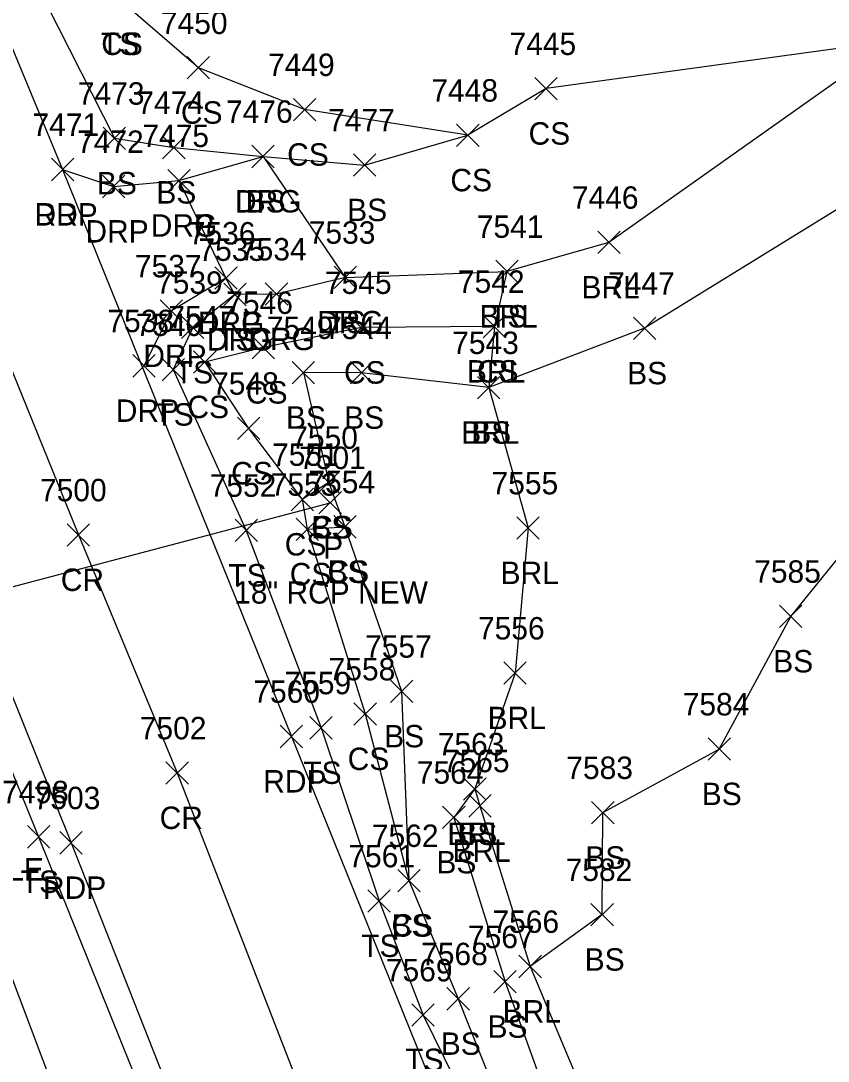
# Model space of a CAD drawing. Extents: x 1472233 to 1475777, y 540726 to 543442.
# Drawn here: x 1472800.2 to 1472872.2, y 540921.2 to 541014 of the extents above; entities that cross this region are included whole.
import ezdxf

# ---------------------------------------------------------------- set-up
doc = ezdxf.new("R2010")
doc.units = 0
for name, color, linetype in [('D_A', 7, 'Continuous'), ('D_C', 7, 'Continuous'), ('D_I', 7, 'Continuous'), ('D_TIC', 7, 'Continuous'), ('DCP', 7, 'Continuous'), ('L_A', 7, 'Continuous'), ('L_C', 7, 'Continuous'), ('L_I', 7, 'Continuous'), ('L_TIC', 7, 'Continuous'), ('LABL', 7, 'Continuous'), ('LELB', 7, 'Continuous'), ('LFNC', 7, 'Continuous'), ('P_A', 7, 'Continuous'), ('P_I', 7, 'Continuous'), ('P_TIC', 7, 'Continuous'), ('PET', 7, 'Continuous'), ('PRC', 7, 'Continuous'), ('R_A', 7, 'Continuous'), ('R_I', 7, 'Continuous'), ('R_TIC', 7, 'Continuous'), ('RDG', 7, 'Continuous'), ('RDP', 7, 'Continuous')]:
    doc.layers.add(name, color=color, linetype=linetype)

msp = doc.modelspace()

# ---------------------------------------------------------------- linework, layer by layer
at = {"layer": 'D_TIC'}
for points in [[(1472826.799, 540969.989), (1472828.799, 540971.989)], [(1472828.799, 540969.989), (1472826.799, 540971.989)]]:
    msp.add_lwpolyline(points, dxfattribs=at)
at = {"layer": 'DCP'}
msp.add_lwpolyline([(1472784.082, 540959.45), (1472827.799, 540970.989)], dxfattribs=at)
at = {"layer": 'L_TIC'}
for points in [[(1472815.038, 541008.798), (1472817.038, 541010.798)], [(1472817.038, 541008.798), (1472815.038, 541010.798)], [(1472846.067, 541006.931), (1472848.067, 541008.931)], [(1472848.067, 541006.931), (1472846.067, 541008.931)], [(1472824.52, 541005.054), (1472826.52, 541007.054)], [(1472826.52, 541005.054), (1472824.52, 541007.054)], [(1472807.54, 541002.497), (1472809.54, 541004.497)], [(1472809.54, 541002.497), (1472807.54, 541004.497)], [(1472839.089, 541002.772), (1472841.089, 541004.772)], [(1472841.089, 541002.772), (1472839.089, 541004.772)], [(1472812.847, 541001.676), (1472814.847, 541003.676)], [(1472814.847, 541001.676), (1472812.847, 541003.676)], [(1472820.816, 541000.878), (1472822.816, 541002.878)], [(1472822.816, 541000.878), (1472820.816, 541002.878)], [(1472829.877, 541000.108), (1472831.877, 541002.108)], [(1472831.877, 541000.108), (1472829.877, 541002.108)], [(1472851.685, 540993.214), (1472853.685, 540995.214)], [(1472853.685, 540993.214), (1472851.685, 540995.214)], [(1472842.58, 540990.617), (1472844.58, 540992.617)], [(1472844.58, 540990.617), (1472842.58, 540992.617)], [(1472842.58, 540990.617), (1472844.58, 540992.617)], [(1472844.58, 540990.617), (1472842.58, 540992.617)], [(1472828.148, 540990.092), (1472830.148, 540992.092)], [(1472830.148, 540990.092), (1472828.148, 540992.092)], [(1472818.305, 540988.563), (1472820.305, 540990.563)], [(1472820.305, 540988.563), (1472818.305, 540990.563)], [(1472814.529, 540985.625), (1472816.529, 540987.625)], [(1472816.529, 540985.625), (1472814.529, 540987.625)], [(1472829.592, 540985.615), (1472831.592, 540987.615)], [(1472831.592, 540985.615), (1472829.592, 540987.615)], [(1472841.46, 540985.708), (1472843.46, 540987.708)], [(1472843.46, 540985.708), (1472841.46, 540987.708)], [(1472841.46, 540985.708), (1472843.46, 540987.708)], [(1472843.46, 540985.708), (1472841.46, 540987.708)], [(1472854.863, 540985.554), (1472856.863, 540987.554)], [(1472856.863, 540985.554), (1472854.863, 540987.554)], [(1472820.841, 540983.832), (1472822.841, 540985.832)], [(1472822.841, 540983.832), (1472820.841, 540985.832)], [(1472812.792, 540981.863), (1472814.792, 540983.863)], [(1472814.792, 540981.863), (1472812.792, 540983.863)], [(1472815.615, 540982.535), (1472817.615, 540984.535)], [(1472817.615, 540982.535), (1472815.615, 540984.535)], [(1472824.415, 540981.599), (1472826.415, 540983.599)], [(1472826.415, 540981.599), (1472824.415, 540983.599)], [(1472829.611, 540981.581), (1472831.611, 540983.581)], [(1472831.611, 540981.581), (1472829.611, 540983.581)], [(1472840.948, 540980.253), (1472842.948, 540982.253)], [(1472842.948, 540980.253), (1472840.948, 540982.253)], [(1472840.948, 540980.253), (1472842.948, 540982.253)], [(1472842.948, 540980.253), (1472840.948, 540982.253)], [(1472819.523, 540976.623), (1472821.523, 540978.623)], [(1472821.523, 540976.623), (1472819.523, 540978.623)], [(1472826.673, 540971.801), (1472828.673, 540973.801)], [(1472828.673, 540971.801), (1472826.673, 540973.801)], [(1472826.673, 540971.801), (1472828.673, 540973.801)], [(1472828.673, 540971.801), (1472826.673, 540973.801)], [(1472824.306, 540970.277), (1472826.306, 540972.277)], [(1472826.306, 540970.277), (1472824.306, 540972.277)], [(1472824.306, 540970.277), (1472826.306, 540972.277)], [(1472826.306, 540970.277), (1472824.306, 540972.277)], [(1472819.307, 540967.515), (1472821.307, 540969.515)], [(1472821.307, 540967.515), (1472819.307, 540969.515)], [(1472824.754, 540967.615), (1472826.754, 540969.615)], [(1472826.754, 540967.615), (1472824.754, 540969.615)], [(1472824.754, 540967.615), (1472826.754, 540969.615)], [(1472826.754, 540967.615), (1472824.754, 540969.615)], [(1472828.118, 540967.833), (1472830.118, 540969.833)], [(1472830.118, 540967.833), (1472828.118, 540969.833)], [(1472828.118, 540967.833), (1472830.118, 540969.833)], [(1472830.118, 540967.833), (1472828.118, 540969.833)], [(1472844.463, 540967.733), (1472846.463, 540969.733)], [(1472846.463, 540967.733), (1472844.463, 540969.733)], [(1472867.901, 540959.845), (1472869.901, 540961.845)], [(1472869.901, 540959.845), (1472867.901, 540961.845)], [(1472843.306, 540954.787), (1472845.306, 540956.787)], [(1472845.306, 540954.787), (1472843.306, 540956.787)], [(1472833.179, 540953.162), (1472835.179, 540955.162)], [(1472835.179, 540953.162), (1472833.179, 540955.162)], [(1472829.923, 540951.139), (1472831.923, 540953.139)], [(1472831.923, 540951.139), (1472829.923, 540953.139)], [(1472825.991, 540949.901), (1472827.991, 540951.901)], [(1472827.991, 540949.901), (1472825.991, 540951.901)], [(1472861.521, 540948.011), (1472863.521, 540950.011)], [(1472863.521, 540948.011), (1472861.521, 540950.011)], [(1472839.708, 540944.454), (1472841.708, 540946.454)], [(1472841.708, 540944.454), (1472839.708, 540946.454)], [(1472839.708, 540944.454), (1472841.708, 540946.454)], [(1472841.708, 540944.454), (1472839.708, 540946.454)], [(1472840.169, 540942.944), (1472842.169, 540944.944)], [(1472842.169, 540942.944), (1472840.169, 540944.944)], [(1472851.133, 540942.341), (1472853.133, 540944.341)], [(1472853.133, 540942.341), (1472851.133, 540944.341)], [(1472837.84, 540941.92), (1472839.84, 540943.92)], [(1472839.84, 540941.92), (1472837.84, 540943.92)], [(1472800.778, 540940.178), (1472802.778, 540942.178)], [(1472802.778, 540940.178), (1472800.778, 540942.178)], [(1472833.83, 540936.279), (1472835.83, 540938.279)], [(1472835.83, 540936.279), (1472833.83, 540938.279)], [(1472833.83, 540936.279), (1472835.83, 540938.279)], [(1472835.83, 540936.279), (1472833.83, 540938.279)], [(1472833.83, 540936.279), (1472835.83, 540938.279)], [(1472835.83, 540936.279), (1472833.83, 540938.279)], [(1472831.161, 540934.463), (1472833.161, 540936.463)], [(1472833.161, 540934.463), (1472831.161, 540936.463)], [(1472851.076, 540933.241), (1472853.076, 540935.241)], [(1472853.076, 540933.241), (1472851.076, 540935.241)], [(1472851.076, 540933.241), (1472853.076, 540935.241)], [(1472853.076, 540933.241), (1472851.076, 540935.241)], [(1472844.647, 540928.613), (1472846.647, 540930.613)], [(1472846.647, 540928.613), (1472844.647, 540930.613)], [(1472842.404, 540927.253), (1472844.404, 540929.253)], [(1472844.404, 540927.253), (1472842.404, 540929.253)], [(1472838.227, 540925.731), (1472840.227, 540927.731)], [(1472840.227, 540925.731), (1472838.227, 540927.731)], [(1472835.088, 540924.284), (1472837.088, 540926.284)], [(1472837.088, 540924.284), (1472835.088, 540926.284)]]:
    msp.add_lwpolyline(points, dxfattribs=at)
at = {"layer": 'LABL'}
msp.add_lwpolyline([(1472934.655, 541070.893), (1472902.081, 541045.593), (1472878.098, 541012.185), (1472852.685, 540994.214), (1472843.58, 540991.617), (1472842.46, 540986.708), (1472841.948, 540981.253), (1472845.463, 540968.733), (1472844.306, 540955.787), (1472840.708, 540945.454), (1472841.169, 540943.944), (1472845.647, 540929.613), (1472856.732, 540903.157), (1472864.122, 540875.89)], dxfattribs=at)
at = {"layer": 'LELB'}
for points in [[(1472694.167, 541336.696), (1472710.287, 541363.82), (1472724.01, 541367.466), (1472732.84, 541358.022), (1472735.8, 541341.686), (1472737.449, 541336.783), (1472738.598, 541320.922), (1472714.319, 541313.691), (1472692.632, 541308.438), (1472692.612, 541304.716), (1472694.988, 541295.507), (1472702.177, 541269.109), (1472714.985, 541232.255), (1472725.569, 541201.652), (1472739.903, 541163.717), (1472759.74, 541112.631), (1472772.204, 541081.833), (1472792.335, 541035.431), (1472808.54, 541003.497), (1472813.847, 541002.676), (1472821.816, 541001.878), (1472830.877, 541001.108)], [(1472670.29, 541260.535), (1472686.415, 541223.334), (1472701.444, 541180.389), (1472718.784, 541138.611), (1472733.582, 541098.786), (1472746.912, 541068.409), (1472763.757, 541024.882), (1472785.71, 540979.265), (1472793.399, 540961.673), (1472801.778, 540941.178), (1472816.419, 540904.832), (1472818.512, 540895.298), (1472814.198, 540883.956), (1472809.696, 540876.261)], [(1473012.541, 541139.744), (1472973.929, 541106.163), (1472947.713, 541083.914), (1472934.655, 541070.893), (1472913.615, 541035.573), (1472885.771, 541005.004), (1472855.863, 540986.554), (1472841.948, 540981.253), (1472830.611, 540982.581), (1472825.415, 540982.599), (1472827.673, 540972.801), (1472829.118, 540968.833), (1472834.179, 540954.162), (1472834.83, 540937.279)], [(1472878.098, 541012.185), (1472847.067, 541007.931), (1472840.089, 541003.772), (1472825.52, 541006.054), (1472816.038, 541009.798), (1472808.929, 541015.933)], [(1472830.877, 541001.108), (1472840.089, 541003.772)], [(1472829.148, 540991.092), (1472843.58, 540991.617)], [(1472819.305, 540989.563), (1472815.529, 540986.625), (1472813.792, 540982.863), (1472820.307, 540968.515), (1472826.991, 540950.901), (1472832.161, 540935.463), (1472836.088, 540925.284), (1472847.393, 540902.304), (1472856.125, 540872.911)], [(1472852.076, 540934.241), (1472852.133, 540943.341), (1472862.521, 540949.011), (1472868.901, 540960.845), (1472886.466, 540982.48), (1472900.227, 540986.595), (1472924.188, 540989.652), (1472936.306, 540957.429)], [(1472842.46, 540986.708), (1472830.592, 540986.615), (1472821.841, 540984.832), (1472816.615, 540983.535), (1472820.523, 540977.623), (1472825.306, 540971.277), (1472825.754, 540968.615), (1472830.923, 540952.139), (1472834.83, 540937.279)], [(1472827.673, 540972.801), (1472825.306, 540971.277)], [(1472825.754, 540968.615), (1472829.118, 540968.833)], [(1472840.708, 540945.454), (1472838.84, 540942.92), (1472843.404, 540928.253), (1472852.876, 540902.047), (1472859.438, 540874.022)], [(1472834.83, 540937.279), (1472839.227, 540926.731), (1472849.327, 540901.317), (1472857.11, 540873.311)], [(1472852.076, 540934.241), (1472845.647, 540929.613)]]:
    msp.add_lwpolyline(points, dxfattribs=at)
at = {"layer": 'LFNC'}
msp.add_lwpolyline([(1472795.796, 540938.094), (1472806.397, 540909.942), (1472809.332, 540901.951)], dxfattribs=at)
at = {"layer": 'P_TIC'}
for points in [[(1472802.92, 540999.712), (1472804.92, 541001.712)], [(1472804.92, 540999.712), (1472802.92, 541001.712)], [(1472804.328, 540967.116), (1472806.328, 540969.116)], [(1472806.328, 540967.116), (1472804.328, 540969.116)], [(1472823.335, 540949.135), (1472825.335, 540951.135)], [(1472825.335, 540949.135), (1472823.335, 540951.135)], [(1472813.147, 540945.879), (1472815.147, 540947.879)], [(1472815.147, 540945.879), (1472813.147, 540947.879)], [(1472803.68, 540939.646), (1472805.68, 540941.646)], [(1472805.68, 540939.646), (1472803.68, 540941.646)]]:
    msp.add_lwpolyline(points, dxfattribs=at)
at = {"layer": 'PET'}
for points in [[(1472697.311, 541267.538), (1472711.092, 541230.886), (1472722.856, 541201.141), (1472737.776, 541162.897), (1472758.044, 541112.1), (1472770.407, 541081.49), (1472789.888, 541034.489), (1472803.92, 541000.712), (1472824.335, 540950.135), (1472844.219, 540900.954), (1472854.974, 540872.188)], [(1472676.203, 541262.983), (1472690.882, 541224.88), (1472707.576, 541182.941), (1472724.138, 541140.869), (1472739.403, 541101.901), (1472752.537, 541070.172), (1472769.423, 541027.837), (1472788.076, 540983.085), (1472796.043, 540962.122), (1472804.68, 540940.646), (1472818.489, 540905.674), (1472822.827, 540894.44), (1472834.107, 540865.53)]]:
    msp.add_lwpolyline(points, dxfattribs=at)
at = {"layer": 'PRC'}
msp.add_lwpolyline([(1472686.993, 541264.398), (1472700.968, 541228.154), (1472717.266, 541187.04), (1472733.85, 541145.792), (1472749.416, 541105.972), (1472761.217, 541076.788), (1472779.652, 541031.291), (1472797.555, 540987.284), (1472805.328, 540968.116), (1472814.147, 540946.879), (1472828.528, 540909.935), (1472844.389, 540869.839)], dxfattribs=at)
at = {"layer": 'R_TIC'}
for points in [[(1472820.816, 541000.878), (1472822.816, 541002.878)], [(1472822.816, 541000.878), (1472820.816, 541002.878)], [(1472802.92, 540999.712), (1472804.92, 541001.712)], [(1472804.92, 540999.712), (1472802.92, 541001.712)], [(1472813.299, 540998.722), (1472815.299, 541000.722)], [(1472815.299, 540998.722), (1472813.299, 541000.722)], [(1472813.299, 540998.722), (1472815.299, 541000.722)], [(1472815.299, 540998.722), (1472813.299, 541000.722)], [(1472807.467, 540998.198), (1472809.467, 541000.198)], [(1472809.467, 540998.198), (1472807.467, 541000.198)], [(1472817.498, 540990.025), (1472819.498, 540992.025)], [(1472819.498, 540990.025), (1472817.498, 540992.025)], [(1472817.498, 540990.025), (1472819.498, 540992.025)], [(1472819.498, 540990.025), (1472817.498, 540992.025)], [(1472828.148, 540990.092), (1472830.148, 540992.092)], [(1472830.148, 540990.092), (1472828.148, 540992.092)], [(1472818.305, 540988.563), (1472820.305, 540990.563)], [(1472820.305, 540988.563), (1472818.305, 540990.563)], [(1472822.009, 540988.598), (1472824.009, 540990.598)], [(1472824.009, 540988.598), (1472822.009, 540990.598)], [(1472812.633, 540987.095), (1472814.633, 540989.095)], [(1472814.633, 540987.095), (1472812.633, 540989.095)], [(1472810.178, 540982.202), (1472812.178, 540984.202)], [(1472812.178, 540982.202), (1472810.178, 540984.202)]]:
    msp.add_lwpolyline(points, dxfattribs=at)
at = {"layer": 'RDG'}
msp.add_lwpolyline([(1472814.299, 540999.722), (1472821.816, 541001.878), (1472829.148, 540991.092), (1472823.009, 540989.598), (1472819.305, 540989.563), (1472818.498, 540991.025)], dxfattribs=at)
at = {"layer": 'RDP'}
msp.add_lwpolyline([(1472803.92, 541000.712), (1472808.467, 540999.198), (1472814.299, 540999.722), (1472818.498, 540991.025), (1472813.633, 540988.095), (1472811.178, 540983.202)], dxfattribs=at)

# ---------------------------------------------------------------- texts
at = {"layer": 'D_A'}
msp.add_text('P', height=2, dxfattribs=at).set_placement((1472827.177, 540965.989))
at = {"layer": 'D_C'}
msp.add_text('18" RCP NEW', height=2, dxfattribs=at).set_placement((1472819.232, 540961.989))
at = {"layer": 'D_I'}
msp.add_text('7501', height=2, dxfattribs=at).set_placement((1472825.028, 540973.989))
at = {"layer": 'L_A'}
for s, p in [('TS', (1472807.338, 541010.933)), ('CS', (1472807.37, 541010.933)), ('CS', (1472814.479, 541004.798)), ('CS', (1472845.508, 541002.931)), ('CS', (1472823.961, 541001.054)), ('CS', (1472838.53, 540998.772)), ('BS', (1472806.981, 540998.497)), ('BS', (1472812.288, 540997.676)), ('BS', (1472820.257, 540996.878)), ('BS', (1472829.318, 540996.108)), ('BRL', (1472850.229, 540989.214)), ('BRL', (1472841.123, 540986.617)), ('TS', (1472841.99, 540986.617)), ('TS', (1472827.558, 540986.092)), ('TS', (1472817.714, 540984.563)), ('TS', (1472813.938, 540981.625)), ('CS', (1472829.033, 540981.615)), ('BRL', (1472840.004, 540981.708)), ('CS', (1472840.901, 540981.708)), ('BS', (1472854.304, 540981.554)), ('CS', (1472820.282, 540979.832)), ('CS', (1472815.056, 540978.535)), ('TS', (1472812.201, 540977.863)), ('BS', (1472823.856, 540977.599)), ('BS', (1472829.052, 540977.581)), ('BS', (1472840.389, 540976.253)), ('BRL', (1472839.492, 540976.253)), ('CS', (1472818.964, 540972.623)), ('CS', (1472826.114, 540967.801)), ('BS', (1472826.114, 540967.801)), ('CS', (1472823.747, 540966.277)), ('CS', (1472823.747, 540966.277)), ('TS', (1472818.717, 540963.515)), ('CS', (1472824.195, 540963.615)), ('CS', (1472824.195, 540963.615)), ('CS', (1472827.559, 540963.833)), ('BS', (1472827.559, 540963.833)), ('BRL', (1472843.007, 540963.733)), ('BS', (1472867.341, 540955.845)), ('BRL', (1472841.849, 540950.787)), ('BS', (1472832.62, 540949.162)), ('CS', (1472829.364, 540947.139)), ('TS', (1472825.4, 540945.901)), ('BS', (1472860.962, 540944.011)), ('BRL', (1472838.251, 540940.454)), ('BS', (1472839.149, 540940.454)), ('BRL', (1472838.712, 540938.944)), ('BS', (1472850.574, 540938.341)), ('BS', (1472837.281, 540937.92)), ('TS', (1472800.188, 540936.178)), ('CS', (1472833.271, 540932.279)), ('BS', (1472833.271, 540932.279)), ('BS', (1472833.271, 540932.279)), ('TS', (1472830.57, 540930.463)), ('BS', (1472850.517, 540929.241)), ('BS', (1472850.517, 540929.241)), ('BRL', (1472843.19, 540924.613)), ('BS', (1472841.845, 540923.253)), ('BS', (1472837.668, 540921.731)), ('TS', (1472834.498, 540920.284))]:
    msp.add_text(s, height=2, dxfattribs=at).set_placement(p)
at = {"layer": 'L_C'}
msp.add_text('S.APPLE', height=2, dxfattribs=at).set_placement((1472791.095, 540937.279))
at = {"layer": 'L_I'}
for s, p in [('7450', (1472812.692, 541012.798)), ('7445', (1472843.807, 541010.931)), ('7449', (1472822.253, 541009.054)), ('7473', (1472805.281, 541006.497)), ('7448', (1472836.83, 541006.772)), ('7474', (1472810.588, 541005.676)), ('7476', (1472818.501, 541004.878)), ('7477', (1472827.617, 541004.108)), ('7446', (1472849.37, 540997.214)), ('7533', (1472825.888, 540994.092)), ('7541', (1472840.887, 540994.617)), ('7541', (1472840.887, 540994.617)), ('7535', (1472816.045, 540992.563)), ('7539', (1472812.261, 540989.625)), ('7545', (1472827.333, 540989.615)), ('7542', (1472839.201, 540989.708)), ('7542', (1472839.201, 540989.708)), ('7447', (1472852.603, 540989.554)), ('7546', (1472818.526, 540987.832)), ('7547', (1472813.355, 540986.535)), ('7540', (1472810.445, 540985.863)), ('7549', (1472822.148, 540985.599)), ('7544', (1472827.351, 540985.581)), ('7543', (1472838.689, 540984.253)), ('7543', (1472838.689, 540984.253)), ('7548', (1472817.263, 540980.623)), ('7550', (1472824.327, 540975.801)), ('7550', (1472824.327, 540975.801)), ('7551', (1472822.613, 540974.277)), ('7551', (1472822.613, 540974.277)), ('7553', (1472822.494, 540971.615)), ('7553', (1472822.494, 540971.615)), ('7554', (1472825.858, 540971.833)), ('7554', (1472825.858, 540971.833)), ('7555', (1472842.203, 540971.733)), ('7552', (1472817.047, 540971.515)), ('7585', (1472865.641, 540963.845)), ('7556', (1472840.991, 540958.787)), ('7557', (1472830.919, 540957.162)), ('7558', (1472827.663, 540955.139)), ('7559', (1472823.723, 540953.901)), ('7584', (1472859.261, 540952.011)), ('7563', (1472837.401, 540948.454)), ('7563', (1472837.401, 540948.454)), ('7565', (1472837.862, 540946.944)), ('7564', (1472835.533, 540945.92)), ('7583', (1472848.873, 540946.341)), ('7498', (1472798.518, 540944.178)), ('7562', (1472831.523, 540940.279)), ('7562', (1472831.523, 540940.279)), ('7562', (1472831.523, 540940.279)), ('7561', (1472829.421, 540938.463)), ('7582', (1472848.817, 540937.241)), ('7582', (1472848.817, 540937.241)), ('7566', (1472842.285, 540932.613)), ('7567', (1472840.097, 540931.253)), ('7568', (1472835.92, 540929.731)), ('7569', (1472832.773, 540928.284))]:
    msp.add_text(s, height=2, dxfattribs=at).set_placement(p)
at = {"layer": 'P_A'}
for s, p in [('RDP', (1472801.408, 540995.712)), ('CR', (1472803.761, 540963.116)), ('RDP', (1472821.824, 540945.135)), ('CR', (1472812.58, 540941.879)), ('RDP', (1472802.168, 540935.646))]:
    msp.add_text(s, height=2, dxfattribs=at).set_placement(p)
at = {"layer": 'P_I'}
for s, p in [('7471', (1472801.227, 541003.712)), ('7500', (1472801.902, 540971.116)), ('7560', (1472820.942, 540953.135)), ('7502', (1472810.809, 540949.879)), ('7503', (1472801.341, 540943.646))]:
    msp.add_text(s, height=2, dxfattribs=at).set_placement(p)
at = {"layer": 'R_A'}
for s, p in [('DRG', (1472819.304, 540996.878)), ('DRP', (1472801.408, 540995.712)), ('DRP', (1472805.956, 540994.198)), ('DRG', (1472811.787, 540994.722)), ('DRP', (1472811.787, 540994.722)), ('DRG', (1472815.986, 540986.025)), ('DRP', (1472815.986, 540986.025)), ('DRG', (1472826.636, 540986.092)), ('DRG', (1472816.793, 540984.563)), ('DRG', (1472820.497, 540984.598)), ('DRP', (1472811.121, 540983.095)), ('DRP', (1472808.666, 540978.202))]:
    msp.add_text(s, height=2, dxfattribs=at).set_placement(p)
at = {"layer": 'R_I'}
for s, p in [('7476', (1472818.501, 541004.878)), ('7471', (1472801.227, 541003.712)), ('7475', (1472811.039, 541002.722)), ('7475', (1472811.039, 541002.722)), ('7472', (1472805.208, 541002.198)), ('7536', (1472815.183, 540994.025)), ('7536', (1472815.183, 540994.025)), ('7533', (1472825.888, 540994.092)), ('7535', (1472816.045, 540992.563)), ('7534', (1472819.749, 540992.598)), ('7537', (1472810.373, 540991.095)), ('7538', (1472807.918, 540986.202))]:
    msp.add_text(s, height=2, dxfattribs=at).set_placement(p)

doc.saveas('drawing.dxf')
